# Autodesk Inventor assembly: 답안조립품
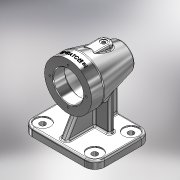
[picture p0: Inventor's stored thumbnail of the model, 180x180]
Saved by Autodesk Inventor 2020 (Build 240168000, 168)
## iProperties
Created: 2024-12
Part Number: 답안조립품
Document SubType Name: Assembly
Designer: 1강의실14
Author: 1강의실14
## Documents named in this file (2)
- C:\Users\1강의실14\Desktop\741204V1019\답안조립품.iam
- C:\Users\1강의실14\Desktop\741204V1019\본체.ipt
